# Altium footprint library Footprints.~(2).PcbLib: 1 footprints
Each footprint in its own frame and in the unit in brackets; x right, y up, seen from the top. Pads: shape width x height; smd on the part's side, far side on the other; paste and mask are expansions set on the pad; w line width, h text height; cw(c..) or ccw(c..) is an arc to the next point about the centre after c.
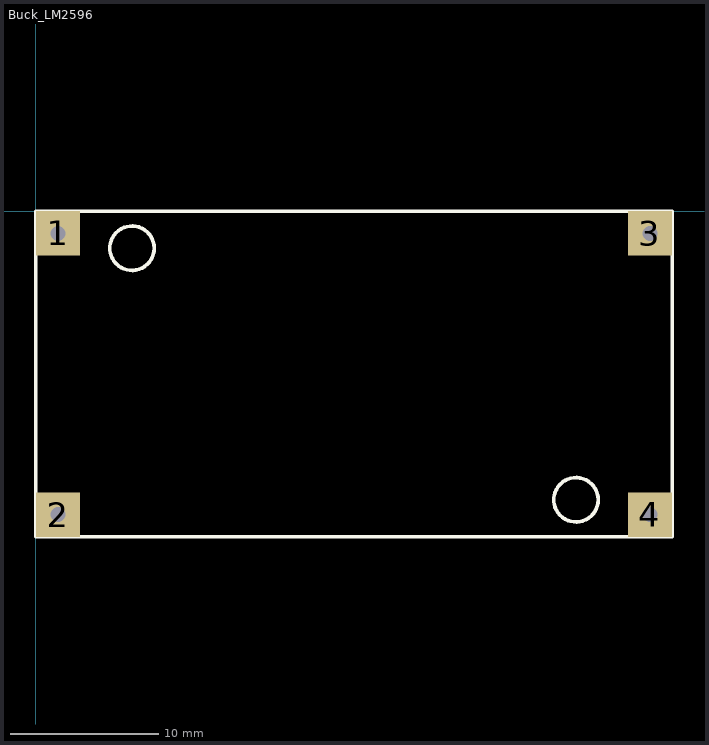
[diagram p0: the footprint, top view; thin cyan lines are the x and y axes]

## Buck_LM2596 [mm]
height 11.5
pads (4):
  rect 3x3 hole 1: 1(1.5,-1.5) 2(1.5,-20.5) 3(41.5,-1.5) 4(41.5,-20.5)
Top Overlay:
  circle w0.254: c36.5,-19.5 r1.5
  circle w0.254: c6.5,-2.5 r1.5
  lines w0.254: 0,-22 0,0 43,0 43,-22 0,-22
